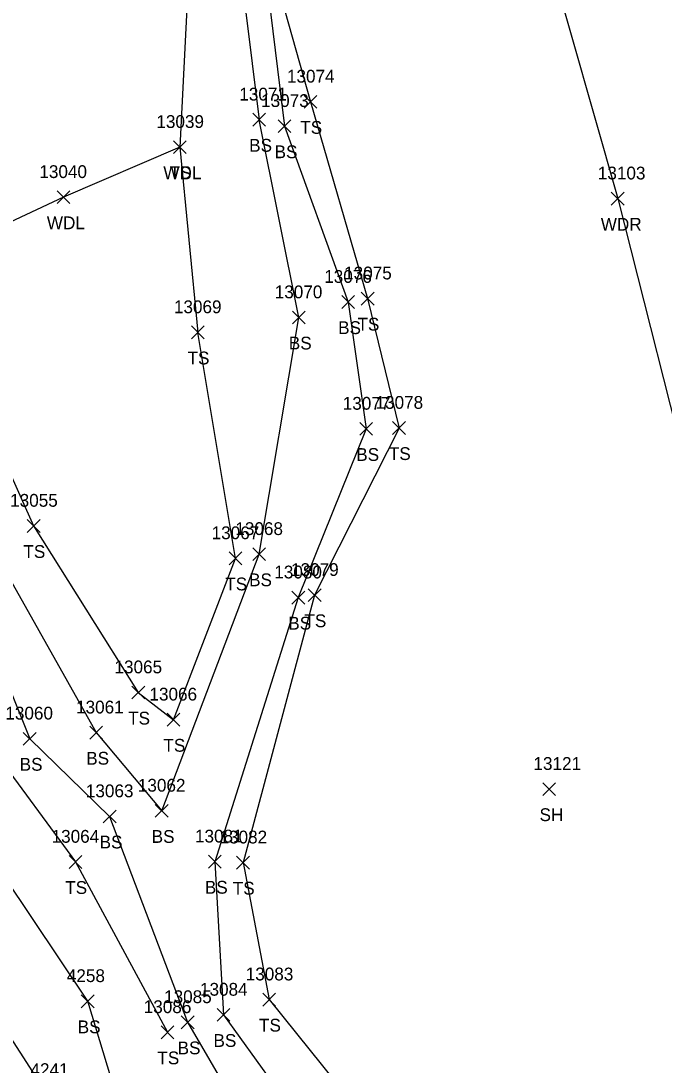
# Model space of a CAD drawing. Extents: x 1482574 to 1485769, y 580696 to 595649.
# Drawn here: x 1483789.5 to 1483889.9, y 583429.1 to 583592.2 of the extents above; entities that cross this region are included whole.
import ezdxf

# ---------------------------------------------------------------- set-up
doc = ezdxf.new("R2010")
doc.units = 0
for name, color, linetype in [('L_A', 7, 'Continuous'), ('L_I', 7, 'Continuous'), ('L_TIC', 7, 'Continuous'), ('LAWA', 7, 'Continuous'), ('LELB', 7, 'Continuous')]:
    doc.layers.add(name, color=color, linetype=linetype)

msp = doc.modelspace()

# ---------------------------------------------------------------- linework, layer by layer
at = {"layer": 'L_TIC'}
for points in [[(1483833.67, 583578.57), (1483835.67, 583580.57)], [(1483835.67, 583578.57), (1483833.67, 583580.57)], [(1483825.66, 583575.77), (1483827.66, 583577.77)], [(1483827.66, 583575.77), (1483825.66, 583577.77)], [(1483825.66, 583575.77), (1483827.66, 583577.77)], [(1483827.66, 583575.77), (1483825.66, 583577.77)], [(1483829.63, 583574.76), (1483831.63, 583576.76)], [(1483831.63, 583574.76), (1483829.63, 583576.76)], [(1483813.28, 583571.48), (1483815.28, 583573.48)], [(1483815.28, 583571.48), (1483813.28, 583573.48)], [(1483813.28, 583571.48), (1483815.28, 583573.48)], [(1483815.28, 583571.48), (1483813.28, 583573.48)], [(1483795.1, 583563.66), (1483797.1, 583565.66)], [(1483797.1, 583563.66), (1483795.1, 583565.66)], [(1483881.64, 583563.44), (1483883.64, 583565.44)], [(1483883.64, 583563.44), (1483881.64, 583565.44)], [(1483839.55, 583547.28), (1483841.55, 583549.28)], [(1483841.55, 583547.28), (1483839.55, 583549.28)], [(1483842.6, 583547.82), (1483844.6, 583549.82)], [(1483844.6, 583547.82), (1483842.6, 583549.82)], [(1483831.85, 583544.87), (1483833.85, 583546.87)], [(1483833.85, 583544.87), (1483831.85, 583546.87)], [(1483816.08, 583542.54), (1483818.08, 583544.54)], [(1483818.08, 583542.54), (1483816.08, 583544.54)], [(1483816.08, 583542.54), (1483818.08, 583544.54)], [(1483818.08, 583542.54), (1483816.08, 583544.54)], [(1483842.38, 583527.46), (1483844.38, 583529.46)], [(1483844.38, 583527.46), (1483842.38, 583529.46)], [(1483847.5, 583527.6), (1483849.5, 583529.6)], [(1483849.5, 583527.6), (1483847.5, 583529.6)], [(1483790.45, 583512.3), (1483792.45, 583514.3)], [(1483792.45, 583512.3), (1483790.45, 583514.3)], [(1483825.65, 583507.88), (1483827.65, 583509.88)], [(1483827.65, 583507.88), (1483825.65, 583509.88)], [(1483821.96, 583507.23), (1483823.96, 583509.23)], [(1483823.96, 583507.23), (1483821.96, 583509.23)], [(1483834.32, 583501.48), (1483836.32, 583503.48)], [(1483836.32, 583501.48), (1483834.32, 583503.48)], [(1483831.77, 583501.1), (1483833.77, 583503.1)], [(1483833.77, 583501.1), (1483831.77, 583503.1)], [(1483806.79, 583486.27), (1483808.79, 583488.27)], [(1483808.79, 583486.27), (1483806.79, 583488.27)], [(1483812.3, 583482.02), (1483814.3, 583484.02)], [(1483814.3, 583482.02), (1483812.3, 583484.02)], [(1483800.22, 583480), (1483802.22, 583482)], [(1483802.22, 583480), (1483800.22, 583482)], [(1483789.83, 583479.05), (1483791.83, 583481.05)], [(1483791.83, 583479.05), (1483789.83, 583481.05)], [(1483870.95, 583471.18), (1483872.95, 583473.18)], [(1483872.95, 583471.18), (1483870.95, 583473.18)], [(1483802.31, 583466.91), (1483804.31, 583468.91)], [(1483804.31, 583466.91), (1483802.31, 583468.91)], [(1483810.44, 583467.78), (1483812.44, 583469.78)], [(1483812.44, 583467.78), (1483810.44, 583469.78)], [(1483796.97, 583459.8), (1483798.97, 583461.8)], [(1483798.97, 583459.8), (1483796.97, 583461.8)], [(1483818.74, 583459.84), (1483820.74, 583461.84)], [(1483820.74, 583459.84), (1483818.74, 583461.84)], [(1483823.14, 583459.69), (1483825.14, 583461.69)], [(1483825.14, 583459.69), (1483823.14, 583461.69)], [(1483798.89, 583438.03), (1483800.89, 583440.03)], [(1483800.89, 583438.03), (1483798.89, 583440.03)], [(1483827.23, 583438.29), (1483829.23, 583440.29)], [(1483829.23, 583438.29), (1483827.23, 583440.29)], [(1483820.09, 583435.9), (1483822.09, 583437.9)], [(1483822.09, 583435.9), (1483820.09, 583437.9)], [(1483814.49, 583434.74), (1483816.49, 583436.74)], [(1483816.49, 583434.74), (1483814.49, 583436.74)], [(1483811.36, 583433.18), (1483813.36, 583435.18)], [(1483813.36, 583433.18), (1483811.36, 583435.18)]]:
    msp.add_lwpolyline(points, dxfattribs=at)
at = {"layer": 'LAWA'}
for points in [[(1483803.2, 583735.12), (1483810.98, 583709.52), (1483815.23, 583662.36), (1483813.44, 583650.62), (1483816.73, 583621.06), (1483814.28, 583572.48), (1483796.1, 583564.66), (1483776.74, 583555.6), (1483769.97, 583556.39), (1483761.33, 583555.43), (1483757.1, 583541.17), (1483756.94, 583537.22), (1483757.07, 583535.35), (1483756.42, 583530.35)], [(1483803.2, 583735.12), (1483825.14, 583713.33), (1483843.38, 583669.74), (1483862.33, 583628.74), (1483871.69, 583603.07), (1483882.64, 583564.44), (1483894.89, 583516.14), (1483900.52, 583463.64), (1483903.73, 583428.05), (1483902.34, 583384.57), (1483914.38, 583350.08), (1483921.77, 583324.12), (1483930.55, 583295.67), (1483924.87, 583287.8)], [(1484017, 583127.07), (1483992.32, 583151.64), (1483986.75, 583162.55), (1483967.23, 583184.52), (1483961.14, 583191.5), (1483958.58, 583194.81), (1483938.8, 583221.92), (1483921.75, 583233.27), (1483898.52, 583261.31), (1483880.67, 583282.01), (1483878.22, 583292.39), (1483867.31, 583307.12), (1483858.51, 583327.08), (1483839.59, 583353.88), (1483824.82, 583372.64), (1483793.64, 583424.35), (1483780.64, 583444.54)]]:
    msp.add_lwpolyline(points, dxfattribs=at)
at = {"layer": 'LELB'}
for points in [[(1483761.1, 583867.79), (1483762.86, 583847.3), (1483769.36, 583823.16), (1483771.13, 583807.85), (1483777.01, 583787.59), (1483781.72, 583760.36), (1483799.95, 583733.64), (1483805.7, 583708.67), (1483815.23, 583662.36), (1483821.18, 583620.83), (1483826.66, 583576.77)], [(1483826.65, 583608.06), (1483830.63, 583575.76), (1483840.55, 583548.28), (1483843.38, 583528.46), (1483832.77, 583502.1), (1483819.74, 583460.84), (1483821.09, 583436.9), (1483844.02, 583405.04), (1483861.88, 583379.64), (1483887.8, 583347.03)], [(1483826.65, 583608.06), (1483834.67, 583579.57), (1483843.6, 583548.82), (1483848.5, 583528.6), (1483835.32, 583502.48), (1483824.14, 583460.69), (1483828.23, 583439.29), (1483851.27, 583410.6), (1483868.55, 583385.67), (1483892.63, 583350.61), (1483900.16, 583331.66), (1483901.04, 583319.94)], [(1483769.97, 583556.39), (1483778.48, 583533.5), (1483783.27, 583512.91), (1483801.22, 583481), (1483811.44, 583468.78), (1483826.65, 583508.88), (1483832.85, 583545.87), (1483826.66, 583576.77)], [(1483814.28, 583572.48), (1483817.08, 583543.54)], [(1483770.53, 583570.38), (1483776.74, 583555.6), (1483781.34, 583535.89), (1483791.45, 583513.3), (1483807.79, 583487.27), (1483813.3, 583483.02), (1483822.96, 583508.23), (1483817.08, 583543.54)], [(1483757.07, 583535.35), (1483767.94, 583535.25), (1483773.76, 583532.37), (1483779.09, 583509.26), (1483790.83, 583480.05), (1483803.31, 583467.91), (1483815.49, 583435.74), (1483836.74, 583399.22), (1483855.98, 583374.23), (1483880.31, 583337.53)], [(1483756.42, 583530.35), (1483767.64, 583532.02), (1483773.96, 583509.32), (1483785.1, 583478.31), (1483797.97, 583460.8), (1483812.36, 583434.18)], [(1483806.06, 583418.71), (1483799.89, 583439.03), (1483786.87, 583458.56), (1483776.26, 583468.77), (1483760.25, 583478.69), (1483754.12, 583500.2), (1483745.11, 583510.72), (1483738.93, 583522.44)]]:
    msp.add_lwpolyline(points, dxfattribs=at)

# ---------------------------------------------------------------- texts
at = {"layer": 'L_A'}
for s, p in [('TS', (1483833.08, 583574.57)), ('BS', (1483825.1, 583571.77)), ('BS', (1483825.1, 583571.77)), ('BS', (1483829.07, 583570.76)), ('WDL', (1483811.7, 583567.48)), ('TS', (1483812.69, 583567.48)), ('WDL', (1483793.51, 583559.66)), ('WDR', (1483880, 583559.44)), ('TS', (1483842.01, 583543.82)), ('BS', (1483838.99, 583543.28)), ('BS', (1483831.29, 583540.87)), ('TS', (1483815.48, 583538.54)), ('TS', (1483815.48, 583538.54)), ('BS', (1483841.82, 583523.46)), ('TS', (1483846.91, 583523.6)), ('TS', (1483789.85, 583508.3)), ('TS', (1483821.37, 583503.23)), ('BS', (1483825.09, 583503.88)), ('BS', (1483831.21, 583497.1)), ('TS', (1483833.73, 583497.48)), ('TS', (1483806.2, 583482.27)), ('TS', (1483811.71, 583478.02)), ('BS', (1483789.27, 583475.05)), ('BS', (1483799.66, 583476)), ('SH', (1483870.44, 583467.18)), ('BS', (1483809.88, 583463.78)), ('BS', (1483801.75, 583462.91)), ('TS', (1483796.38, 583455.8)), ('BS', (1483818.18, 583455.84)), ('TS', (1483822.54, 583455.69)), ('TS', (1483826.64, 583434.29)), ('BS', (1483798.33, 583434.03)), ('BS', (1483819.53, 583431.9)), ('BS', (1483813.93, 583430.74)), ('TS', (1483810.77, 583429.18))]:
    msp.add_text(s, height=2, dxfattribs=at).set_placement(p)
at = {"layer": 'L_I'}
for s, p in [('13074', (1483831, 583582.57)), ('13071', (1483823.56, 583579.77)), ('13071', (1483823.56, 583579.77)), ('13073', (1483826.96, 583578.76)), ('13039', (1483810.61, 583575.48)), ('13039', (1483810.61, 583575.48)), ('13040', (1483792.34, 583567.66)), ('13103', (1483879.54, 583567.44)), ('13075', (1483839.93, 583551.82)), ('13076', (1483836.82, 583551.28)), ('13070', (1483829.09, 583548.87)), ('13069', (1483813.35, 583546.54)), ('13069', (1483813.35, 583546.54)), ('13077', (1483839.71, 583531.46)), ('13078', (1483844.83, 583531.6)), ('13055', (1483787.78, 583516.3)), ('13067', (1483819.24, 583511.23)), ('13068', (1483822.94, 583511.88)), ('13080', (1483829.02, 583505.1)), ('13079', (1483831.64, 583505.48)), ('13065', (1483804.07, 583490.27)), ('13066', (1483809.53, 583486.02)), ('13061', (1483798.07, 583484)), ('13060', (1483787.03, 583483.05)), ('13121', (1483869.49, 583475.18)), ('13062', (1483807.72, 583471.78)), ('13063', (1483799.6, 583470.91)), ('13064', (1483794.25, 583463.8)), ('13081', (1483816.64, 583463.84)), ('13082', (1483820.47, 583463.69)), ('4258', (1483796.63, 583442.03)), ('13083', (1483824.56, 583442.29)), ('13084', (1483817.42, 583439.9)), ('13085', (1483811.82, 583438.74)), ('13086', (1483808.64, 583437.18)), ('4241', (1483790.95, 583427.35))]:
    msp.add_text(s, height=2, dxfattribs=at).set_placement(p)

doc.saveas('drawing.dxf')
